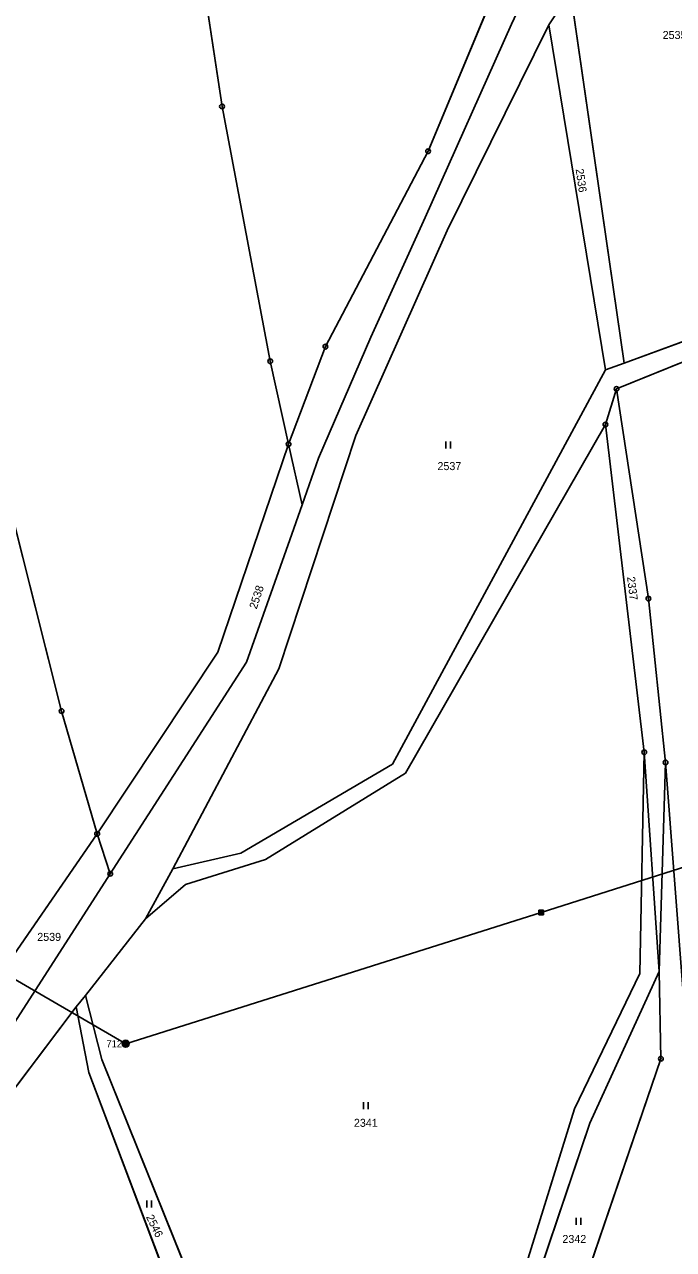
# Model space of a CAD drawing. Extents: x -689422 to -685210, y -987725 to -982160.
# Drawn here: x -688252.7 to -688114.9, y -985398.5 to -985138.3 of the extents above; entities that cross this region are included whole.
import ezdxf

# ---------------------------------------------------------------- set-up
doc = ezdxf.new("R2010")
doc.units = 0
for name, color, linetype in [('KN_Hranice_parcel', 7, 'Continuous'), ('KN_Parcelni cisla', 7, 'Continuous'), ('KN_Polygon parcely', 7, 'Continuous'), ('KN_Pozemkove predmety', 7, 'Continuous'), ('KN_POZEMKY_ORNA PUDA', 7, 'Continuous'), ('KN_POZEMKY_OSTATNI PLOCHA', 7, 'Continuous'), ('KN_POZEMKY_TTP', 7, 'Continuous'), ('KN_VYUZITI_17_ostatni plocha_ostatni komunikace', 7, 'Continuous'), ('KN_VYUZITI_26_ostatni plocha_jina plocha', 7, 'Continuous'), ('KN_Značky bodu BP', 7, 'Continuous'), ('KN_Značky kultur', 7, 'Continuous')]:
    doc.layers.add(name, color=color, linetype=linetype)

msp = doc.modelspace()

# ---------------------------------------------------------------- linework, layer by layer
at = {"layer": 'KN_Hranice_parcel'}
for p, q in [((-688136.81, -985131.46), (-688141.37, -985138.38)), ((-688136.81, -985131.46), (-688125.4, -985210.22)), ((-688141.37, -985138.38), (-688129.33, -985211.65)), ((-688127.01, -985215.71), (-688106.9, -985207.58)), ((-688125.4, -985210.22), (-688129.33, -985211.65)), ((-688129.38, -985223.29), (-688127.01, -985215.71)), ((-688121.12, -985292.9), (-688129.38, -985223.29)), ((-688196.65, -985227.45), (-688193.79, -985240.35)), ((-688117.94, -985339.46), (-688121.12, -985292.9)), ((-688116.59, -985295.07), (-688117.94, -985339.46)), ((-688237.3, -985310.26), (-688259.58, -985342.52)), ((-688237.3, -985310.26), (-688234.51, -985318.71)), ((-688221.21, -985317.65), (-688227.07, -985328.27)), ((-688234.51, -985318.71), (-688256.05, -985352.23)), ((-688227.07, -985328.27), (-688239.75, -985344.56)), ((-688239.75, -985344.56), (-688241.73, -985346.97)), ((-688241.73, -985346.97), (-688280.91, -985398.81))]:
    msp.add_line(p, q, dxfattribs=at)
for points in [[(-688224.38, -984926.86), (-688221.04, -985020.73), (-688224.93, -985025.03), (-688222.87, -985075.69), (-688210.79, -985155.72), (-688200.56, -985209.85), (-688196.65, -985227.45)], [(-688087.14, -984926.53), (-688092.68, -984944.78), (-688114.98, -985000.16), (-688130.72, -985043.38), (-688140.79, -985093.67), (-688146.2, -985115.12), (-688167.04, -985165.22), (-688188.83, -985206.74), (-688196.65, -985227.45)], [(-688289.65, -984933.1), (-688285.47, -985000), (-688275.35, -985141.38), (-688261.8, -985217.11), (-688244.85, -985284.17), (-688237.3, -985310.26)], [(-688123.23, -985035.71), (-688127.97, -985053.84), (-688131.38, -985079.86), (-688132.27, -985098.88), (-688141.81, -985122.23), (-688149.29, -985138.23), (-688167.67, -985179.32), (-688179.19, -985204.7), (-688190.33, -985230.42), (-688193.79, -985240.35)], [(-688141.37, -985138.38), (-688162.96, -985182.09), (-688182.36, -985225.63), (-688198.7, -985275.17), (-688221.21, -985317.65)], [(-688090.83, -985199.79), (-688107.16, -985203.53), (-688125.4, -985210.22)], [(-688129.33, -985211.65), (-688174.57, -985295.43), (-688206.76, -985314.33), (-688221.21, -985317.65)], [(-688127.01, -985215.71), (-688120.25, -985260.26), (-688116.59, -985295.07)], [(-688227.07, -985328.27), (-688218.55, -985320.97), (-688201.52, -985315.68), (-688171.85, -985297.34), (-688129.38, -985223.29)], [(-688196.65, -985227.45), (-688211.7, -985271.62), (-688237.3, -985310.26)], [(-688193.79, -985240.35), (-688196.38, -985247.8), (-688205.62, -985273.78), (-688234.51, -985318.71)], [(-688174.12, -985512.57), (-688159.03, -985454.2), (-688154.29, -985441.47), (-688151.8, -985419.75), (-688135.96, -985368.63), (-688122.04, -985339.91), (-688121.12, -985292.9)], [(-688116.59, -985295.07), (-688112.74, -985345.88), (-688097.3, -985350.44)], [(-688172.09, -985517.46), (-688117.58, -985358), (-688117.94, -985339.46)], [(-688117.94, -985339.46), (-688132.7, -985371.7), (-688148.45, -985418.45), (-688148.83, -985437.59), (-688172.09, -985517.46)], [(-688239.75, -985344.56), (-688236.33, -985358.17), (-688174.12, -985512.57)], [(-688241.73, -985346.97), (-688239.1, -985360.93), (-688201.59, -985459.96)]]:
    msp.add_lwpolyline(points, dxfattribs=at)
at = {"layer": 'KN_Polygon parcely'}
for points in [[(-688087.14, -984926.53), (-688111.99, -984919.35), (-688135.11, -984918.37), (-688224.38, -984926.86), (-688221.04, -985020.73), (-688224.93, -985025.03), (-688222.87, -985075.69), (-688210.79, -985155.72), (-688200.56, -985209.85), (-688196.65, -985227.45), (-688188.83, -985206.74), (-688167.04, -985165.22), (-688146.2, -985115.12), (-688140.79, -985093.67), (-688130.72, -985043.38), (-688114.98, -985000.16), (-688092.68, -984944.78)], [(-688261.8, -985217.11), (-688244.85, -985284.17), (-688237.3, -985310.26), (-688211.7, -985271.62), (-688196.65, -985227.45), (-688200.56, -985209.85), (-688210.79, -985155.72), (-688222.87, -985075.69), (-688224.93, -985025.03), (-688221.04, -985020.73), (-688224.38, -984926.86), (-688289.65, -984933.1), (-688285.47, -985000), (-688275.35, -985141.38)], [(-688305.6, -985192.78), (-688296.5, -985240.18), (-688288, -985264.9), (-688275.45, -985300), (-688259.58, -985342.52), (-688237.3, -985310.26), (-688244.85, -985284.17), (-688261.8, -985217.11), (-688275.35, -985141.38), (-688285.47, -985000), (-688289.65, -984933.1), (-688328.94, -984937.15), (-688324.91, -985000), (-688317.4, -985083.17), (-688308.47, -985166.13)], [(-688119.03, -985049.97), (-688129.53, -985107.03), (-688135, -985127.68), (-688136.81, -985131.46), (-688125.4, -985210.22), (-688107.16, -985203.53), (-688090.83, -985199.79), (-688096.64, -985133.05), (-688101.54, -985049.6)], [(-688141.37, -985138.38), (-688129.33, -985211.65), (-688125.4, -985210.22), (-688136.81, -985131.46)], [(-688198.7, -985275.17), (-688221.21, -985317.65), (-688206.76, -985314.33), (-688174.57, -985295.43), (-688129.33, -985211.65), (-688141.37, -985138.38), (-688162.96, -985182.09), (-688182.36, -985225.63)], [(-688120.25, -985260.26), (-688116.59, -985295.07), (-688112.74, -985345.88), (-688097.3, -985350.44), (-688106.9, -985207.58), (-688127.01, -985215.71)], [(-688127.01, -985215.71), (-688129.38, -985223.29), (-688121.12, -985292.9), (-688117.94, -985339.46), (-688116.59, -985295.07), (-688120.25, -985260.26)], [(-688151.8, -985419.75), (-688135.96, -985368.63), (-688122.04, -985339.91), (-688121.12, -985292.9), (-688129.38, -985223.29), (-688171.85, -985297.34), (-688201.52, -985315.68), (-688218.55, -985320.97), (-688227.07, -985328.27), (-688239.75, -985344.56), (-688236.33, -985358.17), (-688174.12, -985512.57), (-688159.03, -985454.2), (-688154.29, -985441.47)], [(-688234.51, -985318.71), (-688205.62, -985273.78), (-688196.38, -985247.8), (-688193.79, -985240.35), (-688196.65, -985227.45), (-688211.7, -985271.62), (-688237.3, -985310.26)], [(-688121.12, -985292.9), (-688122.04, -985339.91), (-688135.96, -985368.63), (-688151.8, -985419.75), (-688154.29, -985441.47), (-688159.03, -985454.2), (-688174.12, -985512.57), (-688172.09, -985517.46), (-688148.83, -985437.59), (-688148.45, -985418.45), (-688132.7, -985371.7), (-688117.94, -985339.46)], [(-688117.94, -985339.46), (-688117.58, -985358), (-688172.09, -985517.46), (-688164.48, -985537.87), (-688164.68, -985551.96), (-688143.55, -985563.59), (-688107.26, -985579.81), (-688098.45, -985557.71), (-688078.03, -985506.51), (-688053.66, -985437.92), (-688043.57, -985405.26), (-688034.95, -985386.23), (-688023.59, -985374.19), (-688019.27, -985369.61), (-688052.69, -985361.11), (-688076.49, -985356.58), (-688080.38, -985355.43), (-688097.3, -985350.44), (-688112.74, -985345.88), (-688116.59, -985295.07)], [(-688259.58, -985342.52), (-688256.05, -985352.23), (-688234.51, -985318.71), (-688237.3, -985310.26)], [(-688132.7, -985371.7), (-688148.45, -985418.45), (-688148.83, -985437.59), (-688172.09, -985517.46), (-688117.58, -985358), (-688117.94, -985339.46)], [(-688164.68, -985551.96), (-688164.48, -985537.87), (-688172.09, -985517.46), (-688174.12, -985512.57), (-688236.33, -985358.17), (-688239.75, -985344.56), (-688241.73, -985346.97), (-688239.1, -985360.93), (-688201.59, -985459.96), (-688177.68, -985522.98), (-688172.2, -985548.02), (-688168.74, -985549.85)], [(-688280.91, -985398.81), (-688286.21, -985410.27), (-688247.72, -985492.84), (-688232.31, -985520.88), (-688230.1, -985516.5), (-688201.59, -985459.96), (-688239.1, -985360.93), (-688241.73, -985346.97)]]:
    msp.add_lwpolyline(points, close=True, dxfattribs=at)
for points in [[(-688029.34, -984971.05), (-688010.74, -984958.35), (-687992, -984951.88), (-688003.44, -984949.58), (-688006.65, -984951.37), (-688057.41, -984979.74), (-688092.38, -985001.41), (-688112.03, -985015.9), (-688116.44, -985021.01), (-688117.91, -985022.71), (-688123.23, -985035.71), (-688127.97, -985053.84), (-688131.38, -985079.86), (-688132.27, -985098.88), (-688141.81, -985122.23), (-688149.29, -985138.23), (-688167.67, -985179.32), (-688179.19, -985204.7)], [(-688146.2, -985115.12), (-688167.04, -985165.22), (-688188.83, -985206.74), (-688196.65, -985227.45), (-688193.79, -985240.35), (-688190.33, -985230.42), (-688179.19, -985204.7), (-688167.67, -985179.32), (-688149.29, -985138.23)], [(-688386.83, -985617.9), (-688368.15, -985592.34), (-688364.63, -985584.36), (-688355.09, -985562.73), (-688337.65, -985519.73), (-688328.4, -985498.97), (-688316.96, -985473.3), (-688297.75, -985435.26), (-688286.21, -985410.27), (-688280.91, -985398.81), (-688241.73, -985346.97), (-688239.75, -985344.56), (-688227.07, -985328.27), (-688221.21, -985317.65), (-688198.7, -985275.17), (-688182.36, -985225.63), (-688162.96, -985182.09), (-688141.37, -985138.38), (-688136.81, -985131.46)], [(-687954.78, -985204.79), (-687976.96, -985203.07), (-688019.75, -985196.36), (-688054.78, -985192.09), (-688090.83, -985199.79), (-688107.16, -985203.53), (-688125.4, -985210.22), (-688129.33, -985211.65), (-688174.57, -985295.43), (-688206.76, -985314.33), (-688221.21, -985317.65), (-688227.07, -985328.27), (-688218.55, -985320.97), (-688201.52, -985315.68), (-688171.85, -985297.34), (-688129.38, -985223.29), (-688127.01, -985215.71), (-688106.9, -985207.58), (-688090.02, -985203.6), (-688053.94, -985196), (-688020.59, -985199.19), (-687977.1, -985206.05), (-687954.97, -985207.64)], [(-688179.19, -985204.7), (-688190.33, -985230.42), (-688193.79, -985240.35), (-688196.38, -985247.8), (-688205.62, -985273.78), (-688234.51, -985318.71), (-688256.05, -985352.23), (-688257.59, -985354.43), (-688260.02, -985357.88), (-688287.01, -985396.28), (-688287.63, -985397.61), (-688303.9, -985432.39), (-688322.46, -985470.75), (-688333.18, -985494.69), (-688343.32, -985517.35), (-688345.71, -985523.65), (-688359.8, -985560.75), (-688369.82, -985582.29), (-688373.23, -985589.63), (-688388.72, -985611.5), (-688395.08, -985620.47), (-688406.1, -985638.41), (-688418.15, -985657.71)]]:
    msp.add_lwpolyline(points, dxfattribs=at)
at = {"layer": 'KN_Pozemkove predmety'}
for p, q in [((-688143.01, -985326.95), (-688052.79, -985298.24)), ((-688231.24, -985354.82), (-688318.12, -985304.35)), ((-688231.24, -985354.82), (-688143.01, -985326.95)), ((-688143.51, -985326.45), (-688142.51, -985326.45)), ((-688143.51, -985327.45), (-688143.51, -985326.45)), ((-688143.51, -985326.65), (-688142.51, -985326.65)), ((-688143.51, -985326.85), (-688142.51, -985326.85)), ((-688143.51, -985327.05), (-688142.51, -985327.05)), ((-688143.51, -985327.25), (-688142.51, -985327.25)), ((-688143.51, -985327.45), (-688142.51, -985327.45)), ((-688143.31, -985327.45), (-688143.31, -985326.45)), ((-688143.11, -985327.45), (-688143.11, -985326.45)), ((-688142.91, -985327.45), (-688142.91, -985326.45)), ((-688142.71, -985327.45), (-688142.71, -985326.45)), ((-688142.51, -985327.45), (-688142.51, -985326.45)), ((-688231.74, -985354.32), (-688230.74, -985354.32)), ((-688231.74, -985355.32), (-688231.74, -985354.32)), ((-688231.74, -985354.52), (-688230.74, -985354.52)), ((-688231.74, -985354.72), (-688230.74, -985354.72)), ((-688231.74, -985354.92), (-688230.74, -985354.92)), ((-688231.54, -985355.32), (-688231.54, -985354.32)), ((-688231.34, -985355.32), (-688231.34, -985354.32)), ((-688231.14, -985355.32), (-688231.14, -985354.32)), ((-688230.94, -985355.32), (-688230.94, -985354.32)), ((-688230.74, -985355.32), (-688230.74, -985354.32)), ((-688231.74, -985355.12), (-688230.74, -985355.12)), ((-688231.74, -985355.32), (-688230.74, -985355.32))]:
    msp.add_line(p, q, dxfattribs=at)
at = {"layer": 'KN_POZEMKY_ORNA PUDA'}
for p, q in [((-688210.79, -985155.72), (-688222.87, -985075.69)), ((-688222.87, -985075.69), (-688210.79, -985155.72)), ((-688146.2, -985115.12), (-688167.04, -985165.22)), ((-688125.4, -985210.22), (-688136.81, -985131.46)), ((-688200.56, -985209.85), (-688210.79, -985155.72)), ((-688210.79, -985155.72), (-688200.56, -985209.85)), ((-688167.04, -985165.22), (-688188.83, -985206.74)), ((-688107.16, -985203.53), (-688125.4, -985210.22)), ((-688188.83, -985206.74), (-688196.65, -985227.45)), ((-688196.65, -985227.45), (-688200.56, -985209.85)), ((-688200.56, -985209.85), (-688196.65, -985227.45)), ((-688261.8, -985217.11), (-688244.85, -985284.17)), ((-688244.85, -985284.17), (-688261.8, -985217.11)), ((-688196.65, -985227.45), (-688211.7, -985271.62)), ((-688211.7, -985271.62), (-688237.3, -985310.26)), ((-688244.85, -985284.17), (-688237.3, -985310.26)), ((-688237.3, -985310.26), (-688244.85, -985284.17)), ((-688237.3, -985310.26), (-688259.58, -985342.52)), ((-688280.91, -985398.81), (-688241.73, -985346.97)), ((-688241.73, -985346.97), (-688239.1, -985360.93)), ((-688239.1, -985360.93), (-688201.59, -985459.96))]:
    msp.add_line(p, q, dxfattribs=at)
at = {"layer": 'KN_POZEMKY_OSTATNI PLOCHA'}
for p, q in [((-688167.04, -985165.22), (-688146.2, -985115.12)), ((-688141.37, -985138.38), (-688136.81, -985131.46)), ((-688136.81, -985131.46), (-688141.37, -985138.38)), ((-688136.81, -985131.46), (-688125.4, -985210.22)), ((-688149.29, -985138.23), (-688167.67, -985179.32)), ((-688167.67, -985179.32), (-688149.29, -985138.23)), ((-688141.37, -985138.38), (-688162.96, -985182.09)), ((-688129.33, -985211.65), (-688141.37, -985138.38)), ((-688188.83, -985206.74), (-688167.04, -985165.22)), ((-688167.67, -985179.32), (-688179.19, -985204.7)), ((-688179.19, -985204.7), (-688167.67, -985179.32)), ((-688162.96, -985182.09), (-688182.36, -985225.63)), ((-688125.4, -985210.22), (-688107.16, -985203.53)), ((-688179.19, -985204.7), (-688190.33, -985230.42)), ((-688190.33, -985230.42), (-688179.19, -985204.7)), ((-688196.65, -985227.45), (-688188.83, -985206.74)), ((-688106.9, -985207.58), (-688127.01, -985215.71)), ((-688174.57, -985295.43), (-688129.33, -985211.65)), ((-688125.4, -985210.22), (-688129.33, -985211.65)), ((-688129.33, -985211.65), (-688125.4, -985210.22)), ((-688129.38, -985223.29), (-688127.01, -985215.71)), ((-688127.01, -985215.71), (-688129.38, -985223.29)), ((-688127.01, -985215.71), (-688120.25, -985260.26)), ((-688129.38, -985223.29), (-688171.85, -985297.34)), ((-688121.12, -985292.9), (-688129.38, -985223.29)), ((-688211.7, -985271.62), (-688196.65, -985227.45)), ((-688182.36, -985225.63), (-688198.7, -985275.17)), ((-688193.79, -985240.35), (-688196.65, -985227.45)), ((-688196.65, -985227.45), (-688193.79, -985240.35)), ((-688190.33, -985230.42), (-688193.79, -985240.35)), ((-688193.79, -985240.35), (-688190.33, -985230.42)), ((-688193.79, -985240.35), (-688196.38, -985247.8)), ((-688196.38, -985247.8), (-688193.79, -985240.35)), ((-688196.38, -985247.8), (-688205.62, -985273.78)), ((-688205.62, -985273.78), (-688196.38, -985247.8)), ((-688120.25, -985260.26), (-688116.59, -985295.07)), ((-688237.3, -985310.26), (-688211.7, -985271.62)), ((-688205.62, -985273.78), (-688234.51, -985318.71)), ((-688234.51, -985318.71), (-688205.62, -985273.78)), ((-688198.7, -985275.17), (-688221.21, -985317.65)), ((-688122.04, -985339.91), (-688121.12, -985292.9)), ((-688117.94, -985339.46), (-688121.12, -985292.9)), ((-688121.12, -985292.9), (-688117.94, -985339.46)), ((-688116.59, -985295.07), (-688117.94, -985339.46)), ((-688206.76, -985314.33), (-688174.57, -985295.43)), ((-688171.85, -985297.34), (-688201.52, -985315.68)), ((-688259.58, -985342.52), (-688237.3, -985310.26)), ((-688237.3, -985310.26), (-688234.51, -985318.71)), ((-688234.51, -985318.71), (-688237.3, -985310.26)), ((-688221.21, -985317.65), (-688206.76, -985314.33)), ((-688201.52, -985315.68), (-688218.55, -985320.97)), ((-688221.21, -985317.65), (-688227.07, -985328.27)), ((-688227.07, -985328.27), (-688221.21, -985317.65)), ((-688234.51, -985318.71), (-688256.05, -985352.23)), ((-688256.05, -985352.23), (-688234.51, -985318.71)), ((-688218.55, -985320.97), (-688227.07, -985328.27)), ((-688227.07, -985328.27), (-688239.75, -985344.56)), ((-688135.96, -985368.63), (-688122.04, -985339.91)), ((-688117.94, -985339.46), (-688132.7, -985371.7)), ((-688239.75, -985344.56), (-688241.73, -985346.97)), ((-688241.73, -985346.97), (-688280.91, -985398.81)), ((-688151.8, -985419.75), (-688135.96, -985368.63)), ((-688132.7, -985371.7), (-688148.45, -985418.45))]:
    msp.add_line(p, q, dxfattribs=at)
at = {"layer": 'KN_POZEMKY_TTP'}
for p, q in [((-688162.96, -985182.09), (-688141.37, -985138.38)), ((-688141.37, -985138.38), (-688129.33, -985211.65)), ((-688182.36, -985225.63), (-688162.96, -985182.09)), ((-688127.01, -985215.71), (-688106.9, -985207.58)), ((-688129.33, -985211.65), (-688174.57, -985295.43)), ((-688120.25, -985260.26), (-688127.01, -985215.71)), ((-688171.85, -985297.34), (-688129.38, -985223.29)), ((-688129.38, -985223.29), (-688121.12, -985292.9)), ((-688198.7, -985275.17), (-688182.36, -985225.63)), ((-688116.59, -985295.07), (-688120.25, -985260.26)), ((-688221.21, -985317.65), (-688198.7, -985275.17)), ((-688121.12, -985292.9), (-688122.04, -985339.91)), ((-688117.94, -985339.46), (-688116.59, -985295.07)), ((-688112.74, -985345.88), (-688116.59, -985295.07)), ((-688116.59, -985295.07), (-688112.74, -985345.88)), ((-688174.57, -985295.43), (-688206.76, -985314.33)), ((-688201.52, -985315.68), (-688171.85, -985297.34)), ((-688206.76, -985314.33), (-688221.21, -985317.65)), ((-688218.55, -985320.97), (-688201.52, -985315.68)), ((-688227.07, -985328.27), (-688218.55, -985320.97)), ((-688239.75, -985344.56), (-688227.07, -985328.27)), ((-688122.04, -985339.91), (-688135.96, -985368.63)), ((-688132.7, -985371.7), (-688117.94, -985339.46)), ((-688117.94, -985339.46), (-688117.58, -985358)), ((-688117.58, -985358), (-688117.94, -985339.46)), ((-688241.73, -985346.97), (-688239.75, -985344.56)), ((-688236.33, -985358.17), (-688239.75, -985344.56)), ((-688239.75, -985344.56), (-688236.33, -985358.17)), ((-688239.1, -985360.93), (-688241.73, -985346.97)), ((-688174.12, -985512.57), (-688236.33, -985358.17)), ((-688236.33, -985358.17), (-688174.12, -985512.57)), ((-688117.58, -985358), (-688172.09, -985517.46)), ((-688172.09, -985517.46), (-688117.58, -985358)), ((-688201.59, -985459.96), (-688239.1, -985360.93)), ((-688135.96, -985368.63), (-688151.8, -985419.75)), ((-688148.45, -985418.45), (-688132.7, -985371.7))]:
    msp.add_line(p, q, dxfattribs=at)
at = {"layer": 'KN_VYUZITI_17_ostatni plocha_ostatni komunikace'}
for p, q in [((-688167.04, -985165.22), (-688146.2, -985115.12)), ((-688141.37, -985138.38), (-688136.81, -985131.46)), ((-688136.81, -985131.46), (-688141.37, -985138.38)), ((-688136.81, -985131.46), (-688125.4, -985210.22)), ((-688149.29, -985138.23), (-688167.67, -985179.32)), ((-688167.67, -985179.32), (-688149.29, -985138.23)), ((-688141.37, -985138.38), (-688162.96, -985182.09)), ((-688129.33, -985211.65), (-688141.37, -985138.38)), ((-688188.83, -985206.74), (-688167.04, -985165.22)), ((-688167.67, -985179.32), (-688179.19, -985204.7)), ((-688179.19, -985204.7), (-688167.67, -985179.32)), ((-688162.96, -985182.09), (-688182.36, -985225.63)), ((-688125.4, -985210.22), (-688107.16, -985203.53)), ((-688179.19, -985204.7), (-688190.33, -985230.42)), ((-688190.33, -985230.42), (-688179.19, -985204.7)), ((-688196.65, -985227.45), (-688188.83, -985206.74)), ((-688106.9, -985207.58), (-688127.01, -985215.71)), ((-688174.57, -985295.43), (-688129.33, -985211.65)), ((-688125.4, -985210.22), (-688129.33, -985211.65)), ((-688129.33, -985211.65), (-688125.4, -985210.22)), ((-688129.38, -985223.29), (-688127.01, -985215.71)), ((-688127.01, -985215.71), (-688129.38, -985223.29)), ((-688127.01, -985215.71), (-688120.25, -985260.26)), ((-688129.38, -985223.29), (-688171.85, -985297.34)), ((-688121.12, -985292.9), (-688129.38, -985223.29)), ((-688182.36, -985225.63), (-688198.7, -985275.17)), ((-688193.79, -985240.35), (-688196.65, -985227.45)), ((-688190.33, -985230.42), (-688193.79, -985240.35)), ((-688193.79, -985240.35), (-688190.33, -985230.42)), ((-688196.38, -985247.8), (-688193.79, -985240.35)), ((-688205.62, -985273.78), (-688196.38, -985247.8)), ((-688120.25, -985260.26), (-688116.59, -985295.07)), ((-688234.51, -985318.71), (-688205.62, -985273.78)), ((-688198.7, -985275.17), (-688221.21, -985317.65)), ((-688122.04, -985339.91), (-688121.12, -985292.9)), ((-688117.94, -985339.46), (-688121.12, -985292.9)), ((-688121.12, -985292.9), (-688117.94, -985339.46)), ((-688116.59, -985295.07), (-688117.94, -985339.46)), ((-688206.76, -985314.33), (-688174.57, -985295.43)), ((-688171.85, -985297.34), (-688201.52, -985315.68)), ((-688221.21, -985317.65), (-688206.76, -985314.33)), ((-688201.52, -985315.68), (-688218.55, -985320.97)), ((-688221.21, -985317.65), (-688227.07, -985328.27)), ((-688227.07, -985328.27), (-688221.21, -985317.65)), ((-688256.05, -985352.23), (-688234.51, -985318.71)), ((-688218.55, -985320.97), (-688227.07, -985328.27)), ((-688227.07, -985328.27), (-688239.75, -985344.56)), ((-688135.96, -985368.63), (-688122.04, -985339.91)), ((-688117.94, -985339.46), (-688132.7, -985371.7)), ((-688239.75, -985344.56), (-688241.73, -985346.97)), ((-688241.73, -985346.97), (-688280.91, -985398.81)), ((-688151.8, -985419.75), (-688135.96, -985368.63)), ((-688132.7, -985371.7), (-688148.45, -985418.45))]:
    msp.add_line(p, q, dxfattribs=at)
at = {"layer": 'KN_VYUZITI_26_ostatni plocha_jina plocha'}
for p, q in [((-688211.7, -985271.62), (-688196.65, -985227.45)), ((-688196.65, -985227.45), (-688193.79, -985240.35)), ((-688193.79, -985240.35), (-688196.38, -985247.8)), ((-688196.38, -985247.8), (-688205.62, -985273.78)), ((-688237.3, -985310.26), (-688211.7, -985271.62)), ((-688205.62, -985273.78), (-688234.51, -985318.71)), ((-688259.58, -985342.52), (-688237.3, -985310.26)), ((-688237.3, -985310.26), (-688234.51, -985318.71)), ((-688234.51, -985318.71), (-688237.3, -985310.26)), ((-688234.51, -985318.71), (-688256.05, -985352.23))]:
    msp.add_line(p, q, dxfattribs=at)
at = {"layer": 'KN_Značky bodu BP'}
for centre, radius in [((-688210.79, -985155.72), 0.5), ((-688210.79, -985155.72), 0.0303), ((-688167.04, -985165.22), 0.5), ((-688167.04, -985165.22), 0.0303), ((-688188.83, -985206.74), 0.5), ((-688188.83, -985206.74), 0.0303), ((-688200.56, -985209.85), 0.5), ((-688200.56, -985209.85), 0.0303), ((-688127.01, -985215.71), 0.5), ((-688127.01, -985215.71), 0.0303), ((-688129.38, -985223.29), 0.5), ((-688129.38, -985223.29), 0.0303), ((-688196.65, -985227.45), 0.5), ((-688196.65, -985227.45), 0.0303), ((-688120.25, -985260.26), 0.5), ((-688120.25, -985260.26), 0.0303), ((-688244.85, -985284.17), 0.5), ((-688244.85, -985284.17), 0.0303), ((-688121.12, -985292.9), 0.5), ((-688121.12, -985292.9), 0.0303), ((-688116.59, -985295.07), 0.5), ((-688116.59, -985295.07), 0.0303), ((-688237.3, -985310.26), 0.5), ((-688237.3, -985310.26), 0.0303), ((-688234.51, -985318.71), 0.5), ((-688234.51, -985318.71), 0.0303), ((-688231.24, -985354.82), 0.75), ((-688231.24, -985354.82), 0.03), ((-688117.58, -985358), 0.5), ((-688117.58, -985358), 0.0303)]:
    msp.add_circle(centre, radius, dxfattribs=at)
at = {"layer": 'KN_Značky kultur'}
for p, q in [((-688163.25, -985228.39), (-688163.25, -985226.89)), ((-688162.25, -985228.39), (-688162.25, -985226.89)), ((-688180.78, -985368.7), (-688180.78, -985367.2)), ((-688179.78, -985368.7), (-688179.78, -985367.2)), ((-688226.73, -985389.63), (-688226.73, -985388.13)), ((-688225.73, -985389.63), (-688225.73, -985388.13)), ((-688135.6, -985393.3), (-688135.6, -985391.8)), ((-688134.6, -985393.3), (-688134.6, -985391.8))]:
    msp.add_line(p, q, dxfattribs=at)

# ---------------------------------------------------------------- texts
at = {"layer": 'KN_Parcelni cisla'}
for s, p in [('2535', (-688117.22, -985141.38)), ('2537', (-688165.04, -985232.96)), ('2539', (-688250.02, -985332.97)), ('2341', (-688182.78, -985372.47)), ('2342', (-688138.51, -985397.14))]:
    msp.add_text(s, height=1.7, dxfattribs=at).set_placement(p)
for s, rotation, p in [('2536', 278, (-688135.7, -985169.06)), ('2337', 277, (-688124.79, -985255.68)), ('2538', 72, (-688203.44, -985262.6)), ('2546', 296, (-688226.97, -985391.62))]:
    msp.add_text(s, height=1.7, rotation=rotation, dxfattribs=at).set_placement(p)
at = {"layer": 'KN_Značky bodu BP'}
msp.add_text('712', height=1.5, dxfattribs=at).set_placement((-688235.34, -985355.57))

doc.saveas('drawing.dxf')
